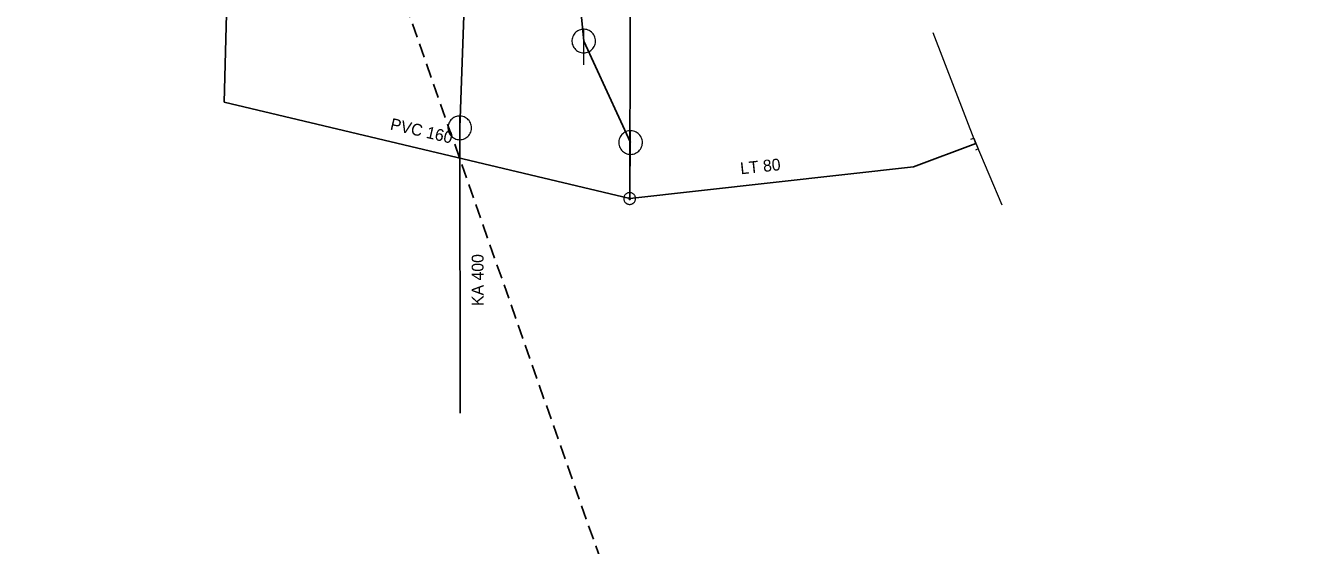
# Model space of a CAD drawing. Extents: x -659250 to -657316, y -997555 to -993684.
# Drawn here: x -658539.7 to -658432.4, y -995635.1 to -995591.1 of the extents above; entities that cross this region are included whole.
import ezdxf

# ---------------------------------------------------------------- set-up
doc = ezdxf.new("R2010")
doc.units = 0
doc.header["$LTSCALE"] = 0.4
doc.linetypes.add('MEDIUM_DASHED', pattern=[4.5, 3, -1.5])
doc.layers.add('1', color=7, linetype='Continuous')
for name, color, linetype, lineweight in [('13', 7, 'Continuous', 13), ('14', 7, 'Continuous', 25), ('17', 7, 'Continuous', 25), ('22', 7, 'Continuous', 13), ('47', 7, 'Continuous', 13), ('63', 7, 'MEDIUM_DASHED', 25)]:
    doc.layers.add(name, color=color, linetype=linetype, lineweight=lineweight)

msp = doc.modelspace()

# ---------------------------------------------------------------- linework, layer by layer
at = {"layer": '13'}
for q in [(-658462.952, -995591.783), (-658457.145, -995606.317)]:
    msp.add_line((-658459.331, -995601.13), q, dxfattribs=at)
at = {"layer": '14'}
for p, q in [((-658502.14, -995575.899), (-658503, -995599.809)), ((-658493.449, -995582.53), (-658492.51, -995592.469)), ((-658492.51, -995592.469), (-658488.55, -995601.05)), ((-658503, -995599.809), (-658502.96, -995623.94))]:
    msp.add_line(p, q, dxfattribs=at)
at = {"layer": '17'}
msp.add_line((-658522.919, -995597.629), (-658488.624, -995605.785), dxfattribs=at)
for points in [[(-658522.919, -995597.629), (-658521.967, -995561.364), (-658525.493, -995533.403), (-658526.434, -995514.37), (-658523.848, -995479.362), (-658526.669, -995461.504), (-658525.493, -995439.824), (-658524.877, -995415.208), (-658524.344, -995415.072)], [(-658488.624, -995605.785), (-658488.504, -995545.309), (-658499.164, -995536.019), (-658510.582, -995535.879)], [(-658488.624, -995605.785), (-658464.629, -995603.09), (-658459.331, -995601.13)]]:
    msp.add_lwpolyline(points, dxfattribs=at)
at = {"layer": '22'}
for p, q in [((-658492.51, -995594.469), (-658492.509, -995591.469)), ((-658503, -995601.809), (-658502.999, -995598.809)), ((-658488.55, -995603.05), (-658488.549, -995600.05))]:
    msp.add_line(p, q, dxfattribs=at)
for points in [[(-658491.51, -995592.469), (-658491.515, -995592.36), (-658491.533, -995592.252), (-658491.563, -995592.146), (-658491.603, -995592.045), (-658491.655, -995591.948), (-658491.717, -995591.858), (-658491.789, -995591.775), (-658491.869, -995591.701), (-658491.957, -995591.635), (-658492.051, -995591.58), (-658492.151, -995591.535), (-658492.256, -995591.502), (-658492.363, -995591.48), (-658492.472, -995591.47), (-658492.582, -995591.472), (-658492.69, -995591.486), (-658492.797, -995591.511), (-658492.9, -995591.548), (-658492.998, -995591.597), (-658493.09, -995591.655), (-658493.176, -995591.724), (-658493.253, -995591.801), (-658493.322, -995591.887), (-658493.381, -995591.979), (-658493.429, -995592.077), (-658493.466, -995592.18), (-658493.492, -995592.287), (-658493.506, -995592.395), (-658493.509, -995592.505), (-658493.499, -995592.614), (-658493.478, -995592.721), (-658493.444, -995592.825), (-658493.4, -995592.925), (-658493.345, -995593.02), (-658493.279, -995593.108), (-658493.205, -995593.188), (-658493.122, -995593.26), (-658493.032, -995593.322), (-658492.936, -995593.374), (-658492.834, -995593.415), (-658492.729, -995593.445), (-658492.621, -995593.463), (-658492.511, -995593.469), (-658492.402, -995593.463), (-658492.294, -995593.445), (-658492.189, -995593.416), (-658492.087, -995593.375), (-658491.99, -995593.323), (-658491.9, -995593.261), (-658491.817, -995593.19), (-658491.742, -995593.11), (-658491.677, -995593.022), (-658491.621, -995592.928), (-658491.577, -995592.828), (-658491.543, -995592.724), (-658491.521, -995592.616), (-658491.511, -995592.507)], [(-658502, -995599.809), (-658502.005, -995599.7), (-658502.023, -995599.592), (-658502.053, -995599.486), (-658502.093, -995599.385), (-658502.145, -995599.288), (-658502.207, -995599.198), (-658502.279, -995599.115), (-658502.359, -995599.041), (-658502.447, -995598.975), (-658502.541, -995598.92), (-658502.641, -995598.875), (-658502.746, -995598.842), (-658502.853, -995598.82), (-658502.962, -995598.81), (-658503.072, -995598.812), (-658503.18, -995598.826), (-658503.287, -995598.851), (-658503.39, -995598.888), (-658503.488, -995598.937), (-658503.58, -995598.995), (-658503.666, -995599.064), (-658503.743, -995599.141), (-658503.812, -995599.227), (-658503.871, -995599.319), (-658503.919, -995599.417), (-658503.956, -995599.52), (-658503.982, -995599.627), (-658503.996, -995599.735), (-658503.999, -995599.845), (-658503.989, -995599.954), (-658503.968, -995600.061), (-658503.934, -995600.165), (-658503.89, -995600.265), (-658503.835, -995600.36), (-658503.769, -995600.448), (-658503.695, -995600.528), (-658503.612, -995600.6), (-658503.522, -995600.662), (-658503.426, -995600.714), (-658503.324, -995600.755), (-658503.219, -995600.785), (-658503.111, -995600.803), (-658503.001, -995600.809), (-658502.892, -995600.803), (-658502.784, -995600.785), (-658502.679, -995600.756), (-658502.577, -995600.715), (-658502.48, -995600.663), (-658502.39, -995600.601), (-658502.307, -995600.53), (-658502.232, -995600.45), (-658502.167, -995600.362), (-658502.111, -995600.268), (-658502.067, -995600.168), (-658502.033, -995600.064), (-658502.011, -995599.956), (-658502.001, -995599.847)], [(-658487.55, -995601.05), (-658487.555, -995600.941), (-658487.573, -995600.833), (-658487.603, -995600.727), (-658487.643, -995600.626), (-658487.695, -995600.529), (-658487.757, -995600.439), (-658487.829, -995600.356), (-658487.909, -995600.282), (-658487.997, -995600.216), (-658488.091, -995600.161), (-658488.191, -995600.116), (-658488.296, -995600.083), (-658488.403, -995600.061), (-658488.512, -995600.051), (-658488.622, -995600.053), (-658488.73, -995600.067), (-658488.837, -995600.092), (-658488.94, -995600.129), (-658489.038, -995600.178), (-658489.13, -995600.236), (-658489.216, -995600.305), (-658489.293, -995600.382), (-658489.362, -995600.468), (-658489.421, -995600.56), (-658489.469, -995600.658), (-658489.506, -995600.761), (-658489.532, -995600.868), (-658489.546, -995600.976), (-658489.549, -995601.086), (-658489.539, -995601.195), (-658489.518, -995601.302), (-658489.484, -995601.406), (-658489.44, -995601.506), (-658489.385, -995601.601), (-658489.319, -995601.689), (-658489.245, -995601.769), (-658489.162, -995601.841), (-658489.072, -995601.903), (-658488.976, -995601.955), (-658488.874, -995601.996), (-658488.769, -995602.026), (-658488.661, -995602.044), (-658488.551, -995602.05), (-658488.442, -995602.044), (-658488.334, -995602.026), (-658488.229, -995601.997), (-658488.127, -995601.956), (-658488.03, -995601.904), (-658487.94, -995601.842), (-658487.857, -995601.771), (-658487.782, -995601.691), (-658487.717, -995601.603), (-658487.661, -995601.509), (-658487.617, -995601.409), (-658487.583, -995601.305), (-658487.561, -995601.197), (-658487.551, -995601.088)]]:
    msp.add_lwpolyline(points, close=True, dxfattribs=at)
at = {"layer": '47'}
msp.add_lwpolyline([(-658459.758, -995600.773), (-658459.526, -995600.674), (-658459.135, -995601.585), (-658459.367, -995601.685)], dxfattribs=at)
for points in [[(-658488.124, -995605.786), (-658488.127, -995605.733), (-658488.135, -995605.681), (-658488.149, -995605.632), (-658488.166, -995605.583), (-658488.191, -995605.536), (-658488.22, -995605.492), (-658488.252, -995605.451), (-658488.289, -995605.414), (-658488.33, -995605.382), (-658488.374, -995605.353), (-658488.421, -995605.328), (-658488.47, -995605.311), (-658488.519, -995605.297), (-658488.571, -995605.289), (-658488.624, -995605.286), (-658488.676, -995605.289), (-658488.728, -995605.297), (-658488.779, -995605.311), (-658488.826, -995605.328), (-658488.874, -995605.353), (-658488.918, -995605.382), (-658488.958, -995605.414), (-658488.995, -995605.451), (-658489.029, -995605.492), (-658489.056, -995605.536), (-658489.081, -995605.583), (-658489.1, -995605.632), (-658489.112, -995605.681), (-658489.12, -995605.733), (-658489.124, -995605.786), (-658489.12, -995605.838), (-658489.112, -995605.89), (-658489.1, -995605.941), (-658489.081, -995605.989), (-658489.056, -995606.036), (-658489.029, -995606.08), (-658488.995, -995606.12), (-658488.958, -995606.157), (-658488.918, -995606.191), (-658488.874, -995606.218), (-658488.826, -995606.243), (-658488.779, -995606.262), (-658488.728, -995606.274), (-658488.676, -995606.282), (-658488.624, -995606.286), (-658488.571, -995606.282), (-658488.519, -995606.274), (-658488.47, -995606.262), (-658488.421, -995606.243), (-658488.374, -995606.218), (-658488.33, -995606.191), (-658488.289, -995606.157), (-658488.252, -995606.12), (-658488.22, -995606.08), (-658488.191, -995606.036), (-658488.166, -995605.989), (-658488.149, -995605.941), (-658488.135, -995605.89), (-658488.127, -995605.838)], [(-658488.541, -995605.786), (-658488.541, -995605.777), (-658488.544, -995605.769), (-658488.546, -995605.761), (-658488.549, -995605.752), (-658488.553, -995605.745), (-658488.558, -995605.738), (-658488.563, -995605.73), (-658488.568, -995605.725), (-658488.576, -995605.72), (-658488.583, -995605.715), (-658488.59, -995605.711), (-658488.598, -995605.708), (-658488.607, -995605.706), (-658488.615, -995605.703), (-658488.624, -995605.703), (-658488.632, -995605.703), (-658488.641, -995605.706), (-658488.649, -995605.708), (-658488.657, -995605.711), (-658488.664, -995605.715), (-658488.671, -995605.72), (-658488.679, -995605.725), (-658488.684, -995605.73), (-658488.691, -995605.738), (-658488.695, -995605.745), (-658488.698, -995605.752), (-658488.701, -995605.761), (-658488.703, -995605.769), (-658488.706, -995605.777), (-658488.706, -995605.786), (-658488.706, -995605.794), (-658488.703, -995605.803), (-658488.701, -995605.811), (-658488.698, -995605.819), (-658488.695, -995605.826), (-658488.691, -995605.833), (-658488.684, -995605.841), (-658488.679, -995605.847), (-658488.671, -995605.853), (-658488.664, -995605.857), (-658488.657, -995605.86), (-658488.649, -995605.864), (-658488.641, -995605.865), (-658488.632, -995605.868), (-658488.624, -995605.868), (-658488.615, -995605.868), (-658488.607, -995605.865), (-658488.598, -995605.864), (-658488.59, -995605.86), (-658488.583, -995605.857), (-658488.576, -995605.853), (-658488.568, -995605.847), (-658488.563, -995605.841), (-658488.558, -995605.833), (-658488.553, -995605.826), (-658488.549, -995605.819), (-658488.546, -995605.811), (-658488.544, -995605.803), (-658488.541, -995605.794)]]:
    msp.add_lwpolyline(points, close=True, dxfattribs=at)
at = {"layer": '63'}
msp.add_lwpolyline([(-659116.685, -993855.266), (-658551.464, -993848.288), (-658551.464, -993848.288), (-657316.352, -997490.822), (-657316.352, -997490.822), (-657839.705, -997490.822), (-657839.705, -997490.822)], close=True, dxfattribs=at)

# ---------------------------------------------------------------- texts
at = {"layer": '1'}
for s, rotation, p in [('PVC 160 ', 347, (-658508.947, -995599.939)), ('LT 80 ', 6, (-658479.22, -995603.737)), ('KA 400', 90, (-658500.989, -995614.871))]:
    msp.add_text(s, height=1, rotation=rotation, dxfattribs=at).set_placement(p)

doc.saveas('drawing.dxf')
